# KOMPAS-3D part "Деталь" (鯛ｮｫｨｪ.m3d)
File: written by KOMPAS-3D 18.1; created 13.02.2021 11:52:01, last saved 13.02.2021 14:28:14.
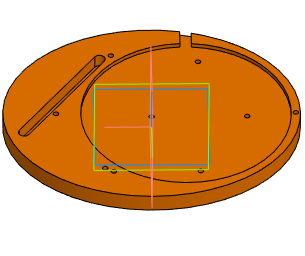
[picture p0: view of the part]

Document properties: Полное имя файла: C:\GoogleDrive\НИР\ИКИ\Компас\Столик.m3d

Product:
- Part/product: Деталь
    Масса: 0.583686

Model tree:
1. Эскиз:1
2. Элемент выдавливания:1
     Расстояние 1 = 8
3. Эскиз:4  (with: Элемент выдавливания:1)
4. Элемент выдавливания:4
     Расстояние 2 = 2
5. Эскиз:5  (with: Элемент выдавливания:1)
6. Элемент выдавливания:5
     Расстояние 2 = 6
7. Эскиз:6  (with: Элемент выдавливания:1)
8. Элемент выдавливания:6
     Расстояние 2 = 8
9. Эскиз:7  (with: Элемент выдавливания:1)
10. Элемент выдавливания:7
     Расстояние 2 = 8
11. Эскиз:8  (with: Элемент выдавливания:1)
12. Элемент выдавливания:8
     Расстояние 2 = 8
